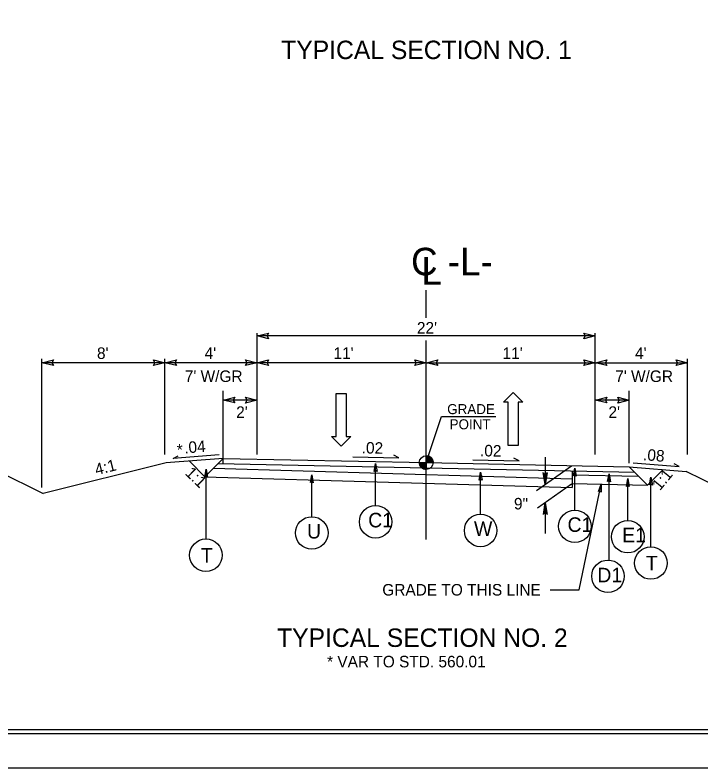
# Model space of a CAD drawing. Extents: x 575722 to 576066, y -53107 to -52774.
# Drawn here: x 575878.83 to 575923.44, y -53106.87 to -53057.85 of the extents above; entities that cross this region are included whole.
import ezdxf

# ---------------------------------------------------------------- set-up
doc = ezdxf.new("R2010")
doc.units = 0
for name, color, linetype in [('Prop Dimension Text', 7, 'Continuous'), ('Prop DSN Text', 7, 'Continuous'), ('Prop Lane Arrow CELL', 7, 'Continuous'), ('Prop Terminator CELL', 7, 'Continuous'), ('Sheet Cutting Line CELL', 7, 'Continuous'), ('Sheet Plot Border Inside CELL', 7, 'Continuous'), ('Sheet Plot Border Outside CELL', 7, 'Continuous'), ('Sheet Typical CELL', 7, 'Continuous'), ('Typical Grade Point Symbol CELL', 7, 'Continuous'), ('Typical ID Circle CELL', 7, 'Continuous'), ('Typical Pavement Slope CELL', 7, 'Continuous'), ('Typical Slope Point Local CELL', 7, 'Continuous'), ('Typical Terminator CELL', 7, 'Continuous'), ('Typical Text Centerline CELL', 7, 'Continuous'), ('Typical Text Grade Point CELL', 7, 'Continuous'), ('Typical Text ID Circle CELL', 7, 'Continuous')]:
    doc.layers.add(name, color=color, linetype=linetype)

# ---------------------------------------------------------------- blocks, each defined once
blk = doc.blocks.new('TERMINATOR')
at = {"layer": 'Typical Terminator CELL'}
blk.add_lwpolyline([(-0.469, 0.081), (0, 0), (-0.471, -0.083), (-0.411, 0)], close=True, dxfattribs=at)

msp = doc.modelspace()

# ---------------------------------------------------------------- linework, layer by layer
at = {"layer": 'Prop Dimension Text'}
for p, q in [((575894.575, -53086.468), (575894.575, -53078.551)), ((575916.575, -53086.468), (575916.575, -53078.551)), ((575916.575, -53078.741), (575894.575, -53078.741)), ((575880.575, -53088.6), (575880.575, -53080.238)), ((575888.575, -53080.488), (575880.575, -53080.488)), ((575888.575, -53085.988), (575888.575, -53080.238)), ((575888.575, -53086.468), (575888.575, -53080.238)), ((575894.575, -53080.488), (575888.575, -53080.488)), ((575894.575, -53085.988), (575894.575, -53080.238)), ((575894.575, -53085.988), (575894.575, -53080.258)), ((575905.575, -53080.488), (575894.575, -53080.488)), ((575905.575, -53080.488), (575916.575, -53080.488)), ((575916.575, -53086.468), (575916.575, -53080.238)), ((575916.575, -53085.988), (575916.575, -53080.238)), ((575916.575, -53085.988), (575916.575, -53080.238)), ((575916.575, -53085.988), (575916.575, -53080.238)), ((575916.575, -53080.488), (575922.575, -53080.488)), ((575922.575, -53086.468), (575922.575, -53080.238)), ((575922.575, -53085.988), (575922.575, -53080.238)), ((575892.369, -53087.027), (575892.369, -53082.314)), ((575918.782, -53087.027), (575918.782, -53082.314)), ((575894.575, -53082.92), (575892.369, -53082.92)), ((575918.782, -53082.92), (575916.575, -53082.92)), ((575890.167, -53086.89), (575891.182, -53087.905)), ((575892.374, -53086.714), (575891.182, -53087.905)), ((575916.587, -53087.22), (575916.583, -53087.224)), ((575919.969, -53088.454), (575918.777, -53087.263)), ((575919.969, -53088.454), (575920.984, -53087.439))]:
    msp.add_line(p, q, dxfattribs=at)
at = {"layer": 'Prop DSN Text'}
for p, q in [((575913.313, -53086.627), (575913.313, -53088.422)), ((575915.019, -53087.227), (575912.741, -53088.823)), ((575913.313, -53088.422), (575913.175, -53087.635)), ((575913.313, -53088.422), (575913.194, -53087.65)), ((575913.214, -53087.665), (575913.313, -53088.422)), ((575913.313, -53088.422), (575913.234, -53087.678)), ((575913.254, -53087.693), (575913.313, -53088.422)), ((575913.313, -53088.422), (575913.274, -53087.708)), ((575913.294, -53087.723), (575913.313, -53088.422)), ((575913.313, -53088.422), (575913.453, -53087.635)), ((575913.434, -53087.65), (575913.313, -53088.422)), ((575913.313, -53088.422), (575913.412, -53087.665)), ((575913.392, -53087.678), (575913.313, -53088.422)), ((575913.313, -53088.422), (575913.373, -53087.693)), ((575913.353, -53087.708), (575913.313, -53088.422)), ((575913.313, -53088.422), (575913.333, -53087.723)), ((575913.313, -53087.737), (575913.313, -53088.422)), ((575915.019, -53088.394), (575912.805, -53089.944)), ((575915.529, -53095.264), (575916.961, -53088.392)), ((575913.313, -53089.588), (575913.175, -53090.376)), ((575913.194, -53090.36), (575913.313, -53089.588)), ((575913.313, -53089.588), (575913.214, -53090.346)), ((575913.234, -53090.331), (575913.313, -53089.588)), ((575913.313, -53089.588), (575913.254, -53090.317)), ((575913.274, -53090.303), (575913.313, -53089.588)), ((575913.313, -53089.588), (575913.294, -53090.288)), ((575913.313, -53089.588), (575913.313, -53091.61)), ((575913.313, -53089.588), (575913.453, -53090.376)), ((575913.313, -53090.274), (575913.313, -53089.588)), ((575913.333, -53090.288), (575913.313, -53089.588)), ((575913.313, -53089.588), (575913.353, -53090.303)), ((575913.373, -53090.317), (575913.313, -53089.588)), ((575913.313, -53089.588), (575913.392, -53090.331)), ((575913.412, -53090.346), (575913.313, -53089.588)), ((575913.313, -53089.588), (575913.434, -53090.36)), ((575913.629, -53095.264), (575915.529, -53095.264))]:
    msp.add_line(p, q, dxfattribs=at)
at = {"layer": 'Prop Lane Arrow CELL'}
for p, q in [((575899.708, -53085.282), (575899.708, -53082.482)), ((575899.708, -53082.482), (575900.368, -53082.482)), ((575900.368, -53082.482), (575900.368, -53085.282)), ((575910.601, -53083.064), (575911.221, -53082.434)), ((575911.221, -53082.434), (575911.861, -53083.064)), ((575910.901, -53083.064), (575910.601, -53083.064)), ((575910.901, -53085.864), (575910.901, -53083.064)), ((575911.861, -53083.064), (575911.561, -53083.064)), ((575911.561, -53083.064), (575911.561, -53085.864)), ((575900.048, -53085.912), (575899.408, -53085.282)), ((575899.408, -53085.282), (575899.708, -53085.282)), ((575900.668, -53085.282), (575900.048, -53085.912)), ((575900.368, -53085.282), (575900.668, -53085.282)), ((575911.561, -53085.864), (575910.901, -53085.864))]:
    msp.add_line(p, q, dxfattribs=at)
at = {"layer": 'Prop Terminator CELL'}
msp.add_lwpolyline([(575916.773, -53088.868), (575916.961, -53088.392), (575916.946, -53088.906), (575916.871, -53088.825)], close=True, dxfattribs=at)
msp.add_lwpolyline([(575916.773, -53088.868), (575916.961, -53088.392), (575916.946, -53088.906), (575916.871, -53088.825)], close=True, dxfattribs=at)
at = {"layer": 'Sheet Cutting Line CELL'}
msp.add_line((575797.38, -53106.867), (575965.78, -53106.867), dxfattribs=at)
at = {"layer": 'Sheet Plot Border Inside CELL'}
msp.add_lwpolyline([(575965.33, -52999.112), (575798.68, -52999.112), (575798.68, -53104.622), (575965.33, -53104.622)], close=True, dxfattribs=at)
at = {"layer": 'Sheet Plot Border Outside CELL'}
msp.add_lwpolyline([(575965.78, -52996.867), (575797.38, -52996.867), (575797.38, -53106.867), (575965.78, -53106.867)], close=True, dxfattribs=at)
at = {"layer": 'Sheet Typical CELL'}
msp.add_lwpolyline([(575964.08, -52999.367), (575814.08, -52999.367), (575814.08, -53104.367), (575964.08, -53104.367)], close=True, dxfattribs=at)
at = {"layer": 'Typical Grade Point Symbol CELL'}
for p, q in [((575905.575, -53086.988), (575906.575, -53083.988)), ((575905.575, -53086.988), (575905.575, -53086.541)), ((575905.128, -53086.988), (575905.575, -53086.988)), ((575905.574, -53087.436), (575905.575, -53086.988)), ((575905.575, -53086.988), (575905.574, -53087.436)), ((575906.023, -53086.988), (575905.575, -53086.988))]:
    msp.add_line(p, q, dxfattribs=at)
for points in [[(575905.579, -53086.541), (575905.579, -53086.541), (575905.579, -53086.988)], [(575905.588, -53086.541), (575905.588, -53086.988)], [(575905.597, -53086.542), (575905.597, -53086.988)], [(575905.606, -53086.542), (575905.606, -53086.988)], [(575905.615, -53086.543), (575905.615, -53086.988)], [(575905.624, -53086.544), (575905.624, -53086.988)], [(575905.633, -53086.545), (575905.633, -53086.988)], [(575905.642, -53086.546), (575905.642, -53086.988)], [(575905.651, -53086.547), (575905.651, -53086.988)], [(575905.66, -53086.549), (575905.66, -53086.988)], [(575905.669, -53086.551), (575905.669, -53086.988)], [(575905.678, -53086.553), (575905.678, -53086.988)], [(575905.687, -53086.555), (575905.687, -53086.988)], [(575905.696, -53086.558), (575905.696, -53086.988)], [(575905.705, -53086.56), (575905.705, -53086.988)], [(575905.714, -53086.563), (575905.714, -53086.988)], [(575905.723, -53086.565), (575905.723, -53086.988)], [(575905.732, -53086.568), (575905.732, -53086.988)], [(575905.741, -53086.572), (575905.741, -53086.988)], [(575905.749, -53086.576), (575905.749, -53086.988)], [(575905.13, -53086.988), (575905.13, -53087.037)], [(575905.139, -53086.988), (575905.139, -53087.09)], [(575905.148, -53086.988), (575905.148, -53087.121)], [(575905.157, -53086.988), (575905.157, -53087.148)], [(575905.166, -53086.988), (575905.166, -53087.169)], [(575905.175, -53086.988), (575905.175, -53087.188)], [(575905.184, -53086.988), (575905.184, -53087.205)], [(575905.192, -53086.988), (575905.192, -53087.221)], [(575905.201, -53086.988), (575905.201, -53087.235)], [(575905.21, -53086.988), (575905.21, -53087.248)], [(575905.219, -53086.988), (575905.219, -53087.26)], [(575905.228, -53086.988), (575905.228, -53087.271)], [(575905.237, -53086.988), (575905.237, -53087.282)], [(575905.246, -53086.988), (575905.246, -53087.292)], [(575905.255, -53086.988), (575905.255, -53087.302)], [(575905.264, -53086.988), (575905.264, -53087.31)], [(575905.273, -53086.988), (575905.273, -53087.318)], [(575905.282, -53086.988), (575905.282, -53087.326)], [(575905.291, -53086.988), (575905.291, -53087.334)], [(575905.3, -53086.988), (575905.3, -53087.341)], [(575905.309, -53086.988), (575905.309, -53087.348)], [(575905.318, -53086.988), (575905.318, -53087.354)], [(575905.327, -53086.988), (575905.327, -53087.36)], [(575905.336, -53086.988), (575905.336, -53087.366)], [(575905.345, -53086.988), (575905.345, -53087.372)], [(575905.354, -53086.988), (575905.354, -53087.377)], [(575905.363, -53086.988), (575905.363, -53087.382)], [(575905.372, -53086.988), (575905.372, -53087.387)], [(575905.38, -53086.988), (575905.38, -53087.391)], [(575905.389, -53086.988), (575905.389, -53087.395)], [(575905.398, -53086.988), (575905.398, -53087.399)], [(575905.407, -53086.988), (575905.407, -53087.403)], [(575905.416, -53086.988), (575905.416, -53087.407)], [(575905.425, -53086.988), (575905.425, -53087.41)], [(575905.434, -53086.988), (575905.434, -53087.413)], [(575905.443, -53086.988), (575905.443, -53087.416)], [(575905.452, -53086.988), (575905.452, -53087.418)], [(575905.461, -53086.988), (575905.461, -53087.421)], [(575905.47, -53086.988), (575905.47, -53087.423)], [(575905.479, -53086.988), (575905.479, -53087.425)], [(575905.488, -53086.988), (575905.488, -53087.427)], [(575905.497, -53086.988), (575905.497, -53087.429)], [(575905.506, -53086.988), (575905.506, -53087.43)], [(575905.515, -53086.988), (575905.515, -53087.432)], [(575905.524, -53086.988), (575905.524, -53087.433)], [(575905.533, -53086.988), (575905.533, -53087.434)], [(575905.542, -53086.988), (575905.542, -53087.435)], [(575905.551, -53086.988), (575905.551, -53087.435)], [(575905.56, -53086.988), (575905.56, -53087.436)], [(575905.568, -53086.988), (575905.568, -53087.436), (575905.568, -53087.436)], [(575905.758, -53086.58), (575905.758, -53086.988)], [(575905.767, -53086.584), (575905.767, -53086.988)], [(575905.776, -53086.588), (575905.776, -53086.988)], [(575905.785, -53086.593), (575905.785, -53086.988)], [(575905.794, -53086.598), (575905.794, -53086.988)], [(575905.803, -53086.603), (575905.803, -53086.988)], [(575905.812, -53086.608), (575905.812, -53086.988)], [(575905.821, -53086.614), (575905.821, -53086.988)], [(575905.83, -53086.62), (575905.83, -53086.988)], [(575905.839, -53086.627), (575905.839, -53086.988)], [(575905.848, -53086.633), (575905.848, -53086.988)], [(575905.857, -53086.64), (575905.857, -53086.988)], [(575905.866, -53086.648), (575905.866, -53086.988)], [(575905.875, -53086.656), (575905.875, -53086.988)], [(575905.884, -53086.664), (575905.884, -53086.988)], [(575905.893, -53086.673), (575905.893, -53086.988)], [(575905.902, -53086.682), (575905.902, -53086.988)], [(575905.911, -53086.692), (575905.911, -53086.988)], [(575905.92, -53086.703), (575905.92, -53086.988)], [(575905.929, -53086.714), (575905.929, -53086.988)], [(575905.937, -53086.726), (575905.937, -53086.988)], [(575905.946, -53086.739), (575905.946, -53086.988)], [(575905.955, -53086.752), (575905.955, -53086.988)], [(575905.964, -53086.767), (575905.964, -53086.988)], [(575905.973, -53086.783), (575905.973, -53086.988)], [(575905.982, -53086.802), (575905.982, -53086.988)], [(575905.991, -53086.823), (575905.991, -53086.988)], [(575906, -53086.848), (575906, -53086.988)], [(575906.009, -53086.879), (575906.009, -53086.988)], [(575906.018, -53086.925), (575906.018, -53086.988)]]:
    msp.add_lwpolyline(points, dxfattribs=at)
msp.add_circle((575905.575, -53086.988), 0.448, dxfattribs=at)
for start, end in [(359.9905, 89.9905), (179.9905, 269.9905)]:
    msp.add_arc((575905.575, -53086.988), 0.448, start, end, dxfattribs=at)
at = {"layer": 'Typical ID Circle CELL'}
for p, q in [((575902.283, -53089.785), (575902.283, -53087.051)), ((575891.252, -53091.961), (575891.252, -53087.421)), ((575915.248, -53090.078), (575915.248, -53087.345)), ((575898.133, -53090.511), (575898.133, -53087.777)), ((575909.114, -53090.347), (575909.114, -53087.613)), ((575917.466, -53093.332), (575917.466, -53087.712)), ((575918.689, -53090.755), (575918.689, -53088.021)), ((575920.196, -53092.47), (575920.196, -53087.93))]:
    msp.add_line(p, q, dxfattribs=at)
for centre in [(575902.283, -53090.842), (575909.113, -53091.404), (575915.248, -53091.136), (575898.133, -53091.569), (575918.689, -53091.813), (575891.245, -53093.019), (575920.189, -53093.528), (575917.398, -53094.388)]:
    msp.add_circle(centre, 1.058, dxfattribs=at)
at = {"layer": 'Typical Pavement Slope CELL'}
for p, q in [((575892.109, -53086.474), (575889.109, -53086.714)), ((575889.109, -53086.714), (575889.442, -53086.547)), ((575903.798, -53086.68), (575903.465, -53086.513)), ((575892.374, -53086.714), (575888.663, -53087.011)), ((575900.798, -53086.617), (575903.798, -53086.68)), ((575908.616, -53086.802), (575911.616, -53086.865)), ((575911.616, -53086.865), (575911.283, -53086.698)), ((575919.037, -53087.004), (575922.037, -53087.244)), ((575915.078, -53087.536), (575915.078, -53088.353)), ((575918.777, -53087.263), (575922.488, -53087.56)), ((575922.037, -53087.244), (575921.704, -53087.077)), ((575915.078, -53088.049), (575915.078, -53088.616))]:
    msp.add_line(p, q, dxfattribs=at)
for points in [[(575892.031, -53087.057), (575905.575, -53087.338)], [(575892.374, -53086.714), (575905.575, -53086.988)], [(575905.575, -53086.988), (575918.777, -53087.263)], [(575891.737, -53087.35), (575915.078, -53088.049)], [(575905.575, -53087.338), (575919.135, -53087.62)], [(575891.182, -53087.905), (575915.078, -53088.616)], [(575915.078, -53087.786), (575919.39, -53087.876)], [(575915.078, -53088.353), (575919.969, -53088.454)]]:
    msp.add_lwpolyline(points, dxfattribs=at)
at = {"layer": 'Typical Slope Point Local CELL'}
for p, q in [((575872.735, -53085.046), (575880.664, -53089.01)), ((575888.663, -53087.011), (575880.664, -53089.01)), ((575933.65, -53093.141), (575922.488, -53087.56))]:
    msp.add_line(p, q, dxfattribs=at)
at = {"layer": 'Typical Terminator CELL'}
for points in [[(575902.194, -53087.566), (575902.283, -53087.051), (575902.375, -53087.569), (575902.283, -53087.503)], [(575891.164, -53087.936), (575891.252, -53087.421), (575891.344, -53087.939), (575891.252, -53087.873)], [(575915.159, -53087.86), (575915.248, -53087.345), (575915.34, -53087.863), (575915.248, -53087.797)], [(575898.044, -53088.293), (575898.133, -53087.777), (575898.224, -53088.295), (575898.133, -53088.23)], [(575909.025, -53088.128), (575909.114, -53087.613), (575909.205, -53088.131), (575909.114, -53088.065)], [(575917.377, -53088.227), (575917.466, -53087.712), (575917.558, -53088.23), (575917.466, -53088.164)], [(575918.6, -53088.537), (575918.689, -53088.021), (575918.78, -53088.539), (575918.689, -53088.474)], [(575920.108, -53088.446), (575920.196, -53087.93), (575920.288, -53088.449), (575920.196, -53088.383)]]:
    msp.add_lwpolyline(points, close=True, dxfattribs=at)
at = {"layer": 'Typical Text Centerline CELL'}
for p, q in [((575905.575, -53077.56), (575905.575, -53075.755)), ((575905.575, -53091.988), (575905.575, -53079.039))]:
    msp.add_line(p, q, dxfattribs=at)
at = {"layer": 'Typical Text Grade Point CELL'}
msp.add_line((575906.575, -53083.988), (575910.113, -53083.988), dxfattribs=at)

# ---------------------------------------------------------------- block references
at = {"layer": 'Prop Dimension Text', "xscale": 1.5906680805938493, "yscale": 2.2831050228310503, "rotation": 180}
for p in [(575894.575, -53078.741), (575880.575, -53080.488), (575888.575, -53080.488), (575894.575, -53080.488), (575905.575, -53080.488), (575916.575, -53080.488), (575892.369, -53082.92), (575916.575, -53082.92)]:
    msp.add_blockref('TERMINATOR', p, dxfattribs=at)
at = {"layer": 'Prop Dimension Text', "xscale": 1.5906680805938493, "yscale": 2.2831050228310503}
for p in [(575916.575, -53078.741), (575888.575, -53080.488), (575894.575, -53080.488), (575905.575, -53080.488), (575916.575, -53080.488), (575922.575, -53080.488), (575894.575, -53082.92), (575918.782, -53082.92)]:
    msp.add_blockref('TERMINATOR', p, dxfattribs=at)

# ---------------------------------------------------------------- texts
at = {"layer": 'Prop Dimension Text'}
for s, height, p in [('TYPICAL SECTION NO. 1', 1.2, (575896.143, -53060.719)), ('TYPICAL SECTION NO. 1', 1.2, (575896.143, -53060.719)), ("22'", 0.75, (575904.971, -53078.585)), ("8'", 0.75, (575884.16, -53080.238)), ("4'", 0.75, (575891.16, -53080.238)), ("11'", 0.75, (575899.543, -53080.238)), ("11'", 0.75, (575910.543, -53080.238)), ("4'", 0.75, (575919.16, -53080.238)), ("7' W/GR", 0.75, (575889.872, -53081.74)), ("7' W/GR", 0.75, (575917.872, -53081.74)), ("2'", 0.75, (575893.214, -53084.076)), ("2'", 0.75, (575917.43, -53084.076)), ('TYPICAL SECTION NO. 2', 1.2, (575895.873, -53098.988))]:
    msp.add_text(s, height=height, dxfattribs=at).set_placement(p)
for s, rotation, p in [('.04', 4.5739, (575889.863, -53086.397)), ('*', 4.5739, (575889.39, -53086.541)), ('.02', 358.8084, (575901.372, -53086.388)), ('.02', 358.8084, (575909.068, -53086.573)), ('.08', 355.4261, (575919.659, -53086.827))]:
    msp.add_text(s, height=0.75, rotation=rotation, dxfattribs=at).set_placement(p)
at = {"layer": 'Prop DSN Text'}
for s, height, p in [('C -L-', 1.7897, (575904.588, -53074.792)), ('L', 1.79, (575905.265, -53075.398)), ('9" ', 0.75, (575911.283, -53090.037)), ('GRADE TO THIS LINE', 0.75, (575902.718, -53095.643)), ('* VAR TO STD. 560.01', 0.75, (575899.127, -53100.318))]:
    msp.add_text(s, height=height, dxfattribs=at).set_placement(p)
at = {"layer": 'Typical Slope Point Local CELL'}
for s, rotation, p in [('4:1', 14.0362, (575884.122, -53087.817)), ('1:1', 316.0532, (575889.843, -53087.727)), ('1:1', 50.5662, (575920.773, -53088.86))]:
    msp.add_text(s, height=0.75, rotation=rotation, dxfattribs=at).set_placement(p)
at = {"layer": 'Typical Text Grade Point CELL'}
for s, p in [('GRADE', (575906.939, -53083.832)), ('POINT', (575907.097, -53084.821))]:
    msp.add_text(s, height=0.6525, dxfattribs=at).set_placement(p)
at = {"layer": 'Typical Text ID Circle CELL'}
for s, height, p in [('C1', 0.9469, (575901.801, -53091.205)), ('U', 0.947, (575897.821, -53091.931)), ('W', 0.947, (575908.682, -53091.767)), ('C1', 0.9469, (575914.766, -53091.499)), ('E1', 0.9469, (575918.322, -53092.175)), ('T', 0.947, (575890.912, -53093.498)), ('T', 0.947, (575919.856, -53094.007)), ('D1', 0.9469, (575916.704, -53094.783))]:
    msp.add_text(s, height=height, dxfattribs=at).set_placement(p)

doc.saveas('drawing.dxf')
